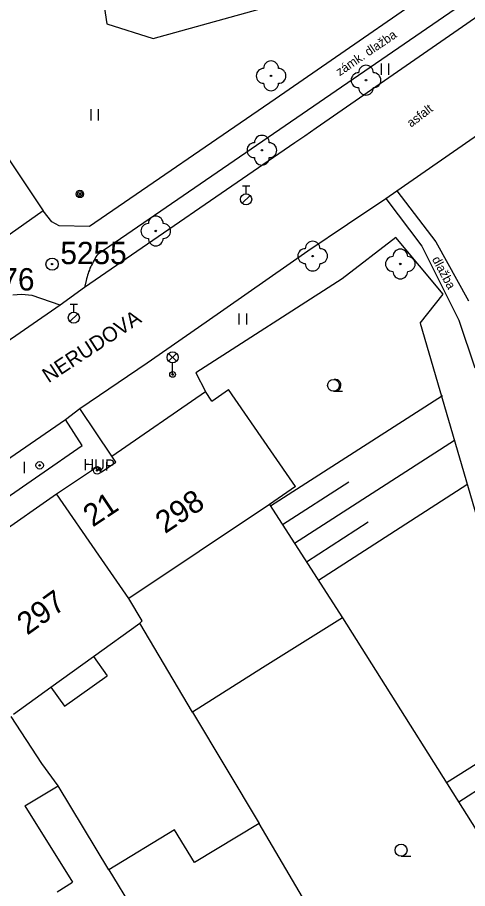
# Model space of a CAD drawing. Extents: x -492431 to -49218, y -1127123 to -112687.
# Drawn here: x -492340 to -492309.7, y -1127091 to -1127032.4 of the extents above; entities that cross this region are included whole.
import ezdxf

# ---------------------------------------------------------------- set-up
doc = ezdxf.new("R2010")
doc.units = 0
for name, color, linetype in [('Vrstva 10', 7, 'Continuous'), ('Vrstva 11', 7, 'Continuous'), ('Vrstva 14', 7, 'Continuous'), ('Vrstva 15', 7, 'Continuous'), ('Vrstva 21', 7, 'Continuous'), ('Vrstva 22', 7, 'Continuous'), ('Vrstva 25', 7, 'Continuous'), ('Vrstva 28', 7, 'Continuous'), ('Vrstva 33', 7, 'Continuous'), ('Vrstva 36', 7, 'Continuous'), ('Vrstva 40', 7, 'Continuous'), ('Vrstva 42', 7, 'Continuous'), ('Vrstva 43', 7, 'Continuous'), ('Vrstva 44', 7, 'Continuous'), ('Vrstva 45', 7, 'Continuous'), ('Vrstva 5', 7, 'Continuous'), ('Vrstva 63', 7, 'Continuous')]:
    doc.layers.add(name, color=color, linetype=linetype)

msp = doc.modelspace()

# ---------------------------------------------------------------- linework, layer by layer
at = {"layer": 'Vrstva 10'}
for p, q in [((-492296.4, -1127022.19), (-492334.53, -1127048.33)), ((-492321.27, -1127040.86), (-492335.44, -1127050.59)), ((-492335.44, -1127050.59), (-492337.07, -1127051.78)), ((-492337.07, -1127051.78), (-492338.96, -1127051.13)), ((-492337.07, -1127051.78), (-492347.66, -1127059.05)), ((-492333.6, -1127061.93), (-492335.76, -1127058.72)), ((-492335.59, -1127061.2), (-492336.73, -1127059.46)), ((-492346.79, -1127068.94), (-492335.59, -1127061.2))]:
    msp.add_line(p, q, dxfattribs=at)
for points in [[(-492368.22, -1127000.44), (-492338.22, -1127045.43)], [(-492308.77, -1127028.34), (-492322.61, -1127037.91), (-492335.11, -1127046.48)], [(-492306.27, -1127030.45), (-492319.84, -1127039.87)], [(-492314.41, -1127044.09), (-492307.59, -1127039.35), (-492300.7, -1127034.57), (-492299.23, -1127034.07), (-492297.76, -1127033.96), (-492296.09, -1127034.31), (-492294.81, -1127034.95), (-492293.43, -1127036.32), (-492292.89, -1127037.2), (-492291.02, -1127043.09), (-492291, -1127044.12), (-492291.3, -1127045.08), (-492291.89, -1127045.92), (-492292.86, -1127046.86)], [(-492319.84, -1127039.87), (-492320.6, -1127040.4), (-492321.27, -1127040.86)], [(-492327.25, -1127052.89), (-492320.4, -1127048.11), (-492317.73, -1127046.32), (-492315.16, -1127044.59)], [(-492315.16, -1127044.59), (-492314.41, -1127044.09)], [(-492315.16, -1127044.59), (-492312.73, -1127047.8), (-492310.23, -1127052.78)], [(-492314.41, -1127044.09), (-492311.78, -1127047.5), (-492309.59, -1127051.48)], [(-492338.22, -1127045.43), (-492340.83, -1127047.27)], [(-492337.65, -1127046.16), (-492338.22, -1127045.43)], [(-492335.11, -1127046.48), (-492337.15, -1127046.44), (-492337.65, -1127046.16)], [(-492334.53, -1127048.33), (-492334.6, -1127048.43), (-492334.67, -1127048.53), (-492334.73, -1127048.64), (-492334.79, -1127048.74), (-492334.85, -1127048.85), (-492334.91, -1127048.96), (-492334.97, -1127049.07), (-492335.02, -1127049.18), (-492335.07, -1127049.29), (-492335.11, -1127049.41), (-492335.16, -1127049.52), (-492335.2, -1127049.64), (-492335.23, -1127049.76), (-492335.27, -1127049.87), (-492335.3, -1127049.99), (-492335.33, -1127050.11), (-492335.44, -1127050.59)], [(-492338.96, -1127051.13), (-492339.69, -1127051.05), (-492340.27, -1127051.1)], [(-492310.23, -1127052.78), (-492309.17, -1127055.98)], [(-492335.76, -1127058.72), (-492331.22, -1127055.64), (-492327.25, -1127052.89)], [(-492336.73, -1127059.46), (-492335.76, -1127058.72)], [(-492344.47, -1127064.77), (-492336.73, -1127059.46)]]:
    msp.add_lwpolyline(points, dxfattribs=at)
at = {"layer": 'Vrstva 11'}
for q in [(-492322.9, -1127061.57), (-492322.98, -1127065.17)]:
    msp.add_line((-492321.24, -1127063.97), q, dxfattribs=at)
for points in [[(-492322.98, -1127065.17), (-492332.46, -1127071.49)], [(-492322.98, -1127065.17), (-492318.08, -1127072.8)], [(-492332.46, -1127071.49), (-492334.47, -1127068.57)], [(-492331.55, -1127073), (-492332.46, -1127071.49)], [(-492334.84, -1127075.4), (-492331.71, -1127073.15)], [(-492331.71, -1127073.15), (-492331.55, -1127073)], [(-492328.16, -1127079.13), (-492331.71, -1127073.15)], [(-492318.08, -1127072.8), (-492323.45, -1127076.15)], [(-492318.08, -1127072.8), (-492307.77, -1127089.11)], [(-492337.7, -1127077.46), (-492334.84, -1127075.4)], [(-492334.84, -1127075.4), (-492333.92, -1127076.69)], [(-492323.45, -1127076.15), (-492328.16, -1127079.13)], [(-492336.78, -1127078.74), (-492333.92, -1127076.69)], [(-492340.22, -1127079.27), (-492337.7, -1127077.46)], [(-492337.7, -1127077.46), (-492336.78, -1127078.74)], [(-492328.16, -1127079.13), (-492323.69, -1127086.63)], [(-492338.31, -1127082.6), (-492340.38, -1127079.43)], [(-492337.21, -1127084.08), (-492338.31, -1127082.6)], [(-492339.45, -1127085.43), (-492337.21, -1127084.08)], [(-492333.81, -1127089.73), (-492337.21, -1127084.08)], [(-492339.45, -1127085.43), (-492336.24, -1127090.58)], [(-492323.69, -1127086.63), (-492328.03, -1127089.25)], [(-492316.57, -1127098.71), (-492323.69, -1127086.63)], [(-492329.37, -1127087.05), (-492333.81, -1127089.73)], [(-492328.03, -1127089.25), (-492329.37, -1127087.05)], [(-492333.81, -1127089.73), (-492332.16, -1127092.44)], [(-492337.29, -1127091.23), (-492336.24, -1127090.58)]]:
    msp.add_lwpolyline(points, dxfattribs=at)
at = {"layer": 'Vrstva 14'}
for p, q in [((-492335.33, -1127023.85), (-492333.93, -1127032.84)), ((-492330.82, -1127033.83), (-492313.3, -1127028.98)), ((-492333.93, -1127032.84), (-492330.82, -1127033.83))]:
    msp.add_line(p, q, dxfattribs=at)
at = {"layer": 'Vrstva 15'}
for p, q in [((-492311.35, -1127057.86), (-492322.91, -1127065.29)), ((-492310.53, -1127060.86), (-492321.3, -1127067.79)), ((-492317.64, -1127063.67), (-492322.1, -1127066.54)), ((-492309.71, -1127063.86), (-492319.69, -1127070.29)), ((-492316.35, -1127066.37), (-492320.5, -1127069.04)), ((-492304.55, -1127079.77), (-492311.07, -1127083.89)), ((-492307.71, -1127083.57), (-492310.25, -1127085.18))]:
    msp.add_line(p, q, dxfattribs=at)
at = {"layer": 'Vrstva 21'}
msp.add_line((-492312.84, -1127052.97), (-492305.85, -1127076.98), dxfattribs=at)
for points in [[(-492312.84, -1127052.97), (-492311.3, -1127051.04), (-492314.47, -1127047.22), (-492318.1, -1127049.99)], [(-492318.1, -1127049.99), (-492327.94, -1127056.32), (-492327.3, -1127057.58)]]:
    msp.add_lwpolyline(points, dxfattribs=at)
at = {"layer": 'Vrstva 22'}
for centre in [(-492322.88, -1127036.35), (-492316.49, -1127036.64), (-492323.5, -1127041.35), (-492330.64, -1127046.78), (-492320.08, -1127048.47), (-492314.18, -1127049)]:
    msp.add_circle(centre, 0.05, dxfattribs=at)
for centre, start, end in [((-492323.38, -1127036.35), 90, 270), ((-492322.88, -1127035.85), 360, 180), ((-492322.38, -1127036.35), 270, 90), ((-492316.49, -1127036.14), 0, 180), ((-492316.99, -1127036.64), 90, 270), ((-492315.99, -1127036.64), 270, 90), ((-492322.88, -1127036.85), 180, 0), ((-492316.49, -1127037.14), 180, 0), ((-492323.5, -1127040.85), 0, 180), ((-492324, -1127041.35), 90, 270), ((-492323, -1127041.35), 270, 90), ((-492323.5, -1127041.85), 180, 0), ((-492330.64, -1127046.28), 0, 180), ((-492331.14, -1127046.78), 90, 270), ((-492330.14, -1127046.78), 270, 90), ((-492330.64, -1127047.28), 180, 0), ((-492320.08, -1127047.97), 360, 180), ((-492320.58, -1127048.47), 90, 270), ((-492319.58, -1127048.47), 270, 90), ((-492314.18, -1127048.5), 360, 180), ((-492314.68, -1127049), 90, 270), ((-492313.68, -1127049), 270, 90), ((-492320.08, -1127048.97), 180, 0), ((-492314.18, -1127049.5), 180, 0)]:
    msp.add_arc(centre, 0.5, start, end, dxfattribs=at)
at = {"layer": 'Vrstva 25'}
for centre, radius in [((-492335.75, -1127044.29), 0.25), ((-492335.75, -1127044.29), 0.158), ((-492335.75, -1127044.29), 0.05), ((-492338.46, -1127062.54), 0.25), ((-492338.46, -1127062.54), 0.05), ((-492334.59, -1127062.88), 0.25), ((-492334.59, -1127062.88), 0.05)]:
    msp.add_circle(centre, radius, dxfattribs=at)
at = {"layer": 'Vrstva 28'}
for p, q in [((-492324.81, -1127043.75), (-492324.31, -1127043.75)), ((-492324.56, -1127044.275), (-492324.56, -1127043.75)), ((-492324.825, -1127044.915), (-492324.295, -1127044.385)), ((-492336.41, -1127051.71), (-492335.91, -1127051.71)), ((-492336.16, -1127052.235), (-492336.16, -1127051.71)), ((-492336.425, -1127052.875), (-492335.895, -1127052.345))]:
    msp.add_line(p, q, dxfattribs=at)
for centre in [(-492324.56, -1127044.65), (-492336.16, -1127052.61)]:
    msp.add_circle(centre, 0.375, dxfattribs=at)
at = {"layer": 'Vrstva 33'}
for p, q in [((-492329.775, -1127055.015), (-492329.245, -1127055.545)), ((-492329.775, -1127055.545), (-492329.245, -1127055.015)), ((-492329.51, -1127056.43), (-492329.51, -1127055.655))]:
    msp.add_line(p, q, dxfattribs=at)
for centre, radius in [((-492329.51, -1127055.28), 0.375), ((-492329.51, -1127056.43), 0.19), ((-492329.51, -1127056.43), 0.05)]:
    msp.add_circle(centre, radius, dxfattribs=at)
at = {"layer": 'Vrstva 36'}
for p, q in [((-492315.45, -1127036.27), (-492315.45, -1127035.52)), ((-492314.95, -1127036.27), (-492314.95, -1127035.52)), ((-492334.99, -1127039.35), (-492334.99, -1127038.6)), ((-492334.49, -1127039.35), (-492334.49, -1127038.6)), ((-492325.02, -1127053.07), (-492325.02, -1127052.32)), ((-492324.52, -1127053.07), (-492324.52, -1127052.32)), ((-492318.68, -1127057.56), (-492318.58, -1127057.56)), ((-492318.58, -1127057.56), (-492318.08, -1127057.56)), ((-492339.48, -1127063.06), (-492339.48, -1127062.31)), ((-492314.132, -1127088.82), (-492313.482, -1127088.817))]:
    msp.add_line(p, q, dxfattribs=at)
for centre, radius in [((-492318.679, -1127057.16), 0.4), ((-492314.132, -1127088.417), 0.403)]:
    msp.add_circle(centre, radius, dxfattribs=at)
msp.add_arc((-492318.579, -1127057.16), 0.4, 259.69515, 97.18076, dxfattribs=at)
at = {"layer": 'Vrstva 5'}
for p, q in [((-492326.86, -1127058.22), (-492325.74, -1127057.45)), ((-492322.9, -1127061.57), (-492325.74, -1127057.45)), ((-492333.6, -1127061.93), (-492327.3, -1127057.58)), ((-492326.86, -1127058.22), (-492327.3, -1127057.58)), ((-492333.34, -1127062.32), (-492333.6, -1127061.93)), ((-492337.32, -1127064.46), (-492334.56, -1127062.62)), ((-492334.32, -1127062.99), (-492334.56, -1127062.62)), ((-492334.32, -1127062.99), (-492333.34, -1127062.32)), ((-492342.24, -1127067.87), (-492337.32, -1127064.46)), ((-492334.47, -1127068.57), (-492337.32, -1127064.46))]:
    msp.add_line(p, q, dxfattribs=at)
at = {"layer": 'Vrstva 63'}
for radius in [0.412, 0.05]:
    msp.add_circle((-492337.62, -1127049.01), radius, dxfattribs=at)

# ---------------------------------------------------------------- texts
at = {"layer": 'Vrstva 40'}
for s, rotation, p in [('zámk. dlažba', 34.3813, (-492318.265, -1127036.388)), ('asfalt', 37.41593, (-492313.456, -1127039.841)), ('dlažba', 298.13062, (-492312.063, -1127048.677))]:
    msp.add_text(s, height=0.6, rotation=rotation, dxfattribs=at).set_placement(p)
at = {"layer": 'Vrstva 42'}
msp.add_text('HUP', height=0.75, rotation=359.19371, dxfattribs=at).set_placement((-492335.52, -1127062.866))
at = {"layer": 'Vrstva 43'}
for s, rotation, p in [('298', 33.68728, (-492330.02, -1127067.175)), ('297', 35.69471, (-492339.294, -1127074))]:
    msp.add_text(s, height=1.5, rotation=rotation, dxfattribs=at).set_placement(p)
at = {"layer": 'Vrstva 44'}
msp.add_text('21', height=1.5, rotation=33.68728, dxfattribs=at).set_placement((-492334.885, -1127066.728))
at = {"layer": 'Vrstva 45'}
msp.add_text('NERUDOVA', height=1, rotation=33.26403, dxfattribs=at).set_placement((-492337.864, -1127057.028))
at = {"layer": 'Vrstva 63'}
for s, p in [(' 5255', (-492337.62, -1127049.01)), (' 576', (-492342.71, -1127050.78))]:
    msp.add_text(s, height=1.5, dxfattribs=at).set_placement(p)

doc.saveas('drawing.dxf')
